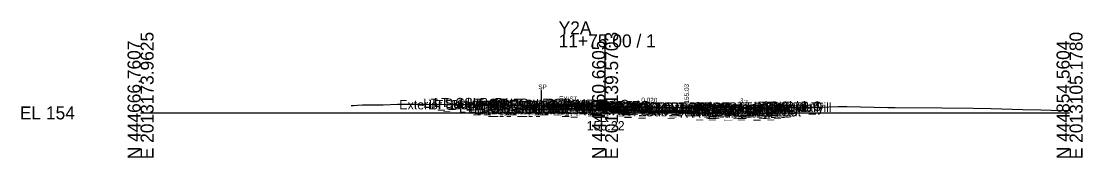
# Model space of a CAD drawing. Extents: x -26 to 203, y -10 to 5517.
# Drawn here: x -25.7 to 202.8, y 3490.3 to 3519.8 of the extents above; entities that cross this region are included whole.
import ezdxf

# ---------------------------------------------------------------- set-up
doc = ezdxf.new("R2010")
doc.units = 0
for name, color, linetype in [('Default', 7, 'Continuous'), ('Exist CMT Pavement', 7, 'Continuous'), ('Exist Cross Section Cell', 7, 'Continuous'), ('Exist XS Center Line Elevation Label', 7, 'Continuous'), ('Exist XS Ground Line', 7, 'Continuous'), ('Prop CMT Conc Surface', 7, 'Continuous'), ('Prop CMT Concrete Structures', 7, 'Continuous'), ('Prop CMT Pvmt Course 1', 7, 'Continuous'), ('Prop CMT Pvmt Course 1 CG', 7, 'Continuous'), ('Prop CMT Pvmt Course 2', 7, 'Continuous'), ('Prop CMT Pvmt Course 3', 7, 'Continuous'), ('Prop CMT Pvmt Surface', 7, 'Continuous'), ('Prop CMT Pvmt Wedge Surface 1', 7, 'Continuous'), ('Prop CMT Pvmt Wedge Surface 2', 7, 'Continuous'), ('Prop CMT Pvmt Wedge Surface 3', 7, 'Continuous'), ('Prop CMT Shear Line', 7, 'Continuous'), ('Prop CMT Slope Grass', 7, 'Continuous'), ('Prop CMT Subgrade Earthwork', 7, 'Continuous'), ('Prop XS Earthwork Shape', 7, 'Continuous'), ('Prop XS Hydro Elevations', 7, 'Continuous'), ('Prop XS SE Text', 7, 'Continuous'), ('Prop XS Side Slope Text', 7, 'Continuous'), ('Scratch_Level_0', 7, 'Continuous')]:
    doc.layers.add(name, color=color, linetype=linetype)

msp = doc.modelspace()

# ---------------------------------------------------------------- linework, layer by layer
at = {"layer": 'Exist CMT Pavement'}
msp.add_lwpolyline([(108.71, 3501.18), (102.91, 3501.28)], dxfattribs=at)
at = {"layer": 'Exist Cross Section Cell'}
for p, q in [((100, 3500), (100, 3516.95)), ((0, 3500), (100, 3500)), ((100, 3500), (200, 3500))]:
    msp.add_line(p, q, dxfattribs=at)
at = {"layer": 'Exist XS Ground Line'}
msp.add_lwpolyline([(45.34, 3501.58), (45.91, 3501.62), (46.67, 3501.66), (47.75, 3501.72), (49.39, 3501.73), (52.22, 3501.74), (55.33, 3501.87), (61.58, 3501.88), (65.98, 3501.85), (70.09, 3501.78), (75.85, 3501.71), (81.76, 3501.63), (82.53, 3501.62), (83.3, 3501.59), (84.88, 3501.52), (85.6, 3502.01), (86.18, 3501.93), (87.4, 3501.89), (90.91, 3501.91), (96.33, 3501.82), (97.35, 3501.79), (98.1, 3501.71), (98.82, 3501.2), (99.54, 3501.21), (100.23, 3501.23), (100.64, 3501.23), (101.31, 3501.23), (101.87, 3501.3), (107.82, 3501.18), (110.39, 3501.18), (113.57, 3501.21), (122.56, 3500.91), (126.51, 3500.76), (127.28, 3500.72), (128.49, 3500.65), (129, 3501.15), (130.13, 3501.15), (132.32, 3501.14), (134.31, 3501.13), (135.45, 3501.13), (146.24, 3501.26), (150.21, 3501.36), (152.02, 3501.36), (160.85, 3501.17), (161.84, 3501.15), (162.42, 3501.14), (172.49, 3501.1), (179.22, 3501.02), (183.14, 3500.96), (189.93, 3500.76), (193.79, 3500.65), (196.03, 3500.61), (200, 3500.55)], dxfattribs=at)
at = {"layer": 'Prop CMT Conc Surface'}
for points in [[(115.54, 3501.15), (117.54, 3501.03)], [(117.54, 3501.03), (117.54, 3501.53), (118.04, 3501.53)]]:
    msp.add_lwpolyline(points, dxfattribs=at)
at = {"layer": 'Prop CMT Concrete Structures'}
for points in [[(98.28, 3501.48), (102.91, 3501.4)], [(115.54, 3501.15), (117.54, 3501.03), (117.54, 3501.53), (118.04, 3501.53)], [(118.04, 3501.53), (118.04, 3500.52), (115.54, 3500.57)], [(115.54, 3500.57), (115.54, 3501.15)], [(127.66, 3501.73), (122.34, 3501.63)], [(122.34, 3501.63), (122.34, 3501.29)], [(122.34, 3501.29), (127.66, 3501.4)], [(127.66, 3501.4), (127.66, 3501.73)]]:
    msp.add_lwpolyline(points, dxfattribs=at)
at = {"layer": 'Prop CMT Pvmt Course 1'}
for points in [[(98.28, 3501.48), (86.29, 3501.6)], [(86.29, 3501.59), (86.29, 3501.42)], [(98.28, 3501.23), (98.28, 3501.48)], [(98.28, 3501.48), (102.91, 3501.4)], [(98.28, 3501.23), (98.28, 3501.48)], [(98.28, 3501.35), (98.28, 3501.23), (98.28, 3501.23)], [(102.91, 3501.15), (98.28, 3501.23)], [(102.91, 3501.4), (115.54, 3501.15)], [(102.91, 3501.15), (102.91, 3501.4)], [(102.91, 3501.4), (102.91, 3501.15)], [(102.91, 3501.28), (102.91, 3501.15), (102.91, 3501.15)], [(114.5, 3500.92), (102.91, 3501.15)], [(115.54, 3501.15), (115.54, 3500.9)], [(115.54, 3500.9), (114.5, 3500.92)]]:
    msp.add_lwpolyline(points, dxfattribs=at)
at = {"layer": 'Prop CMT Pvmt Course 1 CG'}
for points in [[(86.29, 3500.76), (86.29, 3501.09)], [(115.54, 3500.57), (118.54, 3500.51), (118.88, 3500.17)], [(115.54, 3500.23), (115.54, 3500.57)], [(118.88, 3500.17), (115.54, 3500.23)]]:
    msp.add_lwpolyline(points, dxfattribs=at)
at = {"layer": 'Prop CMT Pvmt Course 2'}
for points in [[(86.29, 3501.42), (86.29, 3501.09)], [(86.29, 3501.42), (98.28, 3501.23)], [(86.29, 3501.01), (86.29, 3501.01), (86.29, 3501.34), (86.29, 3501.34)], [(98.28, 3501.23), (102.91, 3501.15)], [(98.28, 3500.89), (98.28, 3501.23)], [(102.91, 3501.15), (102.91, 3500.82)], [(102.91, 3500.82), (98.28, 3500.89)], [(114.5, 3500.92), (115.54, 3500.9)], [(115.54, 3500.57), (114.5, 3500.59)], [(115.54, 3500.9), (115.54, 3500.57)]]:
    msp.add_lwpolyline(points, dxfattribs=at)
at = {"layer": 'Prop CMT Pvmt Course 3'}
for points in [[(86.29, 3501.09), (98.28, 3500.89)], [(98.28, 3500.56), (86.29, 3500.76)], [(98.28, 3500.89), (102.91, 3500.82)], [(98.28, 3500.56), (98.28, 3500.89)], [(102.91, 3500.49), (98.28, 3500.56)], [(102.91, 3500.82), (102.91, 3500.49)], [(102.91, 3500.82), (114.5, 3500.59)], [(115.54, 3500.23), (102.91, 3500.49)], [(114.5, 3500.59), (115.54, 3500.57)], [(115.54, 3500.57), (115.54, 3500.23)]]:
    msp.add_lwpolyline(points, dxfattribs=at)
at = {"layer": 'Prop CMT Pvmt Surface'}
for points in [[(98.28, 3501.48), (86.29, 3501.6)], [(98.28, 3501.48), (102.91, 3501.4)], [(102.91, 3501.4), (115.54, 3501.15)]]:
    msp.add_lwpolyline(points, dxfattribs=at)
at = {"layer": 'Prop CMT Pvmt Wedge Surface 1'}
for points in [[(98.28, 3501.48), (98.28, 3501.23), (98.28, 3501.23), (98.28, 3501.35)], [(102.91, 3501.4), (102.91, 3501.15), (102.91, 3501.15), (102.91, 3501.28)], [(115.54, 3500.9), (115.54, 3501.15)], [(114.5, 3500.92), (115.54, 3500.9)]]:
    msp.add_lwpolyline(points, dxfattribs=at)
at = {"layer": 'Prop CMT Pvmt Wedge Surface 2'}
for points in [[(98.28, 3501.48), (98.28, 3501.23)], [(102.91, 3501.4), (102.91, 3501.15)], [(115.54, 3500.9), (115.54, 3501.15)]]:
    msp.add_lwpolyline(points, dxfattribs=at)
at = {"layer": 'Prop CMT Pvmt Wedge Surface 3'}
for points in [[(98.28, 3501.48), (98.28, 3500.89)], [(102.91, 3501.4), (102.91, 3500.82)], [(115.54, 3500.57), (115.54, 3501.15)]]:
    msp.add_lwpolyline(points, dxfattribs=at)
at = {"layer": 'Prop CMT Shear Line'}
msp.add_line((86.29, 3499.9), (86.29, 3504.99), dxfattribs=at)
at = {"layer": 'Prop CMT Slope Grass'}
for points in [[(118.04, 3501.53), (127.66, 3501.72)], [(127.66, 3501.72), (128.16, 3501.73), (129.92, 3501.15)]]:
    msp.add_lwpolyline(points, dxfattribs=at)
at = {"layer": 'Prop CMT Subgrade Earthwork'}
msp.add_line((86.29, 3500.76), (86.29, 3501.93), dxfattribs=at)
for points in [[(115.54, 3500.23), (118.88, 3500.17), (120.29, 3501.58)], [(86.29, 3500.76), (98.28, 3500.56)], [(98.28, 3500.56), (102.91, 3500.49)], [(102.91, 3500.49), (115.54, 3500.23)]]:
    msp.add_lwpolyline(points, dxfattribs=at)
at = {"layer": 'Prop XS Earthwork Shape'}
for points in [[(98.28, 3501.48), (86.29, 3501.6), (86.29, 3501.93), (87.4, 3501.89), (90.91, 3501.91), (96.33, 3501.82), (97.35, 3501.79), (98.1, 3501.71), (98.28, 3501.58)], [(102.91, 3501.28), (107.82, 3501.18), (108.71, 3501.18), (110.39, 3501.18), (112.93, 3501.2), (115.54, 3501.15), (115.54, 3500.57), (118.04, 3500.52), (118.04, 3501.06), (119.72, 3501.01), (118.88, 3500.17), (115.54, 3500.23), (102.91, 3500.49), (98.28, 3500.56), (86.29, 3500.76), (86.29, 3501.6), (98.28, 3501.48), (98.43, 3501.48), (98.82, 3501.2), (99.54, 3501.21), (100.23, 3501.23), (100.64, 3501.23), (101.31, 3501.23), (101.87, 3501.3)], [(98.28, 3501.58), (98.28, 3501.48), (98.43, 3501.48)], [(100.64, 3501.23), (101.31, 3501.23), (101.87, 3501.3), (102.91, 3501.28), (108.71, 3501.18), (110.39, 3501.18), (112.93, 3501.2), (102.91, 3501.4), (98.43, 3501.48), (98.82, 3501.2), (99.54, 3501.21), (100.23, 3501.23)], [(113.57, 3501.21), (115.54, 3501.15), (112.93, 3501.2)], [(115.54, 3501.15), (115.79, 3501.14), (117.54, 3501.03), (117.54, 3501.08), (118.04, 3501.06), (118.04, 3500.52), (115.54, 3500.57)], [(115.79, 3501.14), (117.54, 3501.08), (117.54, 3501.03)], [(126.51, 3500.76), (127.28, 3500.72), (128.49, 3500.65), (129, 3501.15), (129.92, 3501.15), (128.16, 3501.73), (127.66, 3501.72), (127.66, 3501.4), (122.34, 3501.29), (122.34, 3501.63), (120.29, 3501.58), (119.72, 3501.01), (122.56, 3500.91)]]:
    msp.add_lwpolyline(points, close=True, dxfattribs=at)

# ---------------------------------------------------------------- texts
at = {"layer": 'Default'}
msp.add_text('-', height=0.0001, dxfattribs=at).set_placement((0, 3500))
at = {"layer": 'Exist Cross Section Cell'}
for s, p in [('Y2A', (90, 3516.95)), ('11+75.00 / 1', (90, 3514.15)), ('EL 154', (-26, 3498.6))]:
    msp.add_text(s, height=2.8, dxfattribs=at).set_placement(p)
for s, p in [('E 2013173.9625', (2.8, 3490)), ('E 2013139.5703', (102.8, 3490)), ('E 2013105.1780', (202.8, 3490)), ('N 444666.7607', (0, 3490)), ('N 444760.6605', (100, 3490)), ('N 444854.5604', (200, 3490))]:
    msp.add_text(s, height=2.8, rotation=90, dxfattribs=at).set_placement(p)
at = {"layer": 'Exist XS Center Line Elevation Label'}
msp.add_text('155.22', height=2, dxfattribs=at).set_placement((96.03, 3496.22))
at = {"layer": 'Prop XS Hydro Elevations'}
msp.add_text('SP', height=1, dxfattribs=at).set_placement((85.62, 3505.12))
msp.add_text('155.03', height=1, rotation=90, dxfattribs=at).set_placement((118.04, 3502.03))
at = {"layer": 'Prop XS SE Text'}
for s, rotation, p in [('EXIST', 359.4271, (90.08, 3502.56)), ('0.020', 358.8542, (107.79, 3502.31))]:
    msp.add_text(s, height=1, rotation=rotation, dxfattribs=at).set_placement(p)
at = {"layer": 'Prop XS Side Slope Text'}
msp.add_text('3:1', height=1, rotation=341.5668, dxfattribs=at).set_placement((128.84, 3502.29))
at = {"layer": 'Scratch_Level_0'}
for s, p in [('Exterior Boundary', (55.7, 3500.76)), ('LT_Sub_Trench_Out_DLT', (60.87, 3501.09)), ('LT_Slope_Fill', (62.08, 3500.76)), ('LT_CSLP_Pnt', (63.17, 3501.24)), ('LT_CG1_Shelf_Out', (68.55, 3500.06)), ('LT_PV_Sub_Tie_Out', (69.96, 3500.63)), ('LT_CG_Top_Face', (70.26, 3501.05)), ('LT_CG_Top_BOC', (70.78, 3501.05)), ('LT_CG_Bot_BOC', (70.81, 3500.05)), ('LT_CG_Top_Gut', (71.24, 3500.55)), ('LT_Sub_OEOP', (71.78, 3499.73)), ('LT_Sub_OEOT_CG', (72.37, 3499.69)), ('LT_PV_OEEOP_EG', (72.54, 3500.62)), ('LT_Sub_OEEOP', (74.21, 3499.69)), ('LT_PV2_OEEOP', (74.31, 3500.36)), ('LT_PV3_OEEOP', (74.31, 3500.03)), ('LT_PV1_OEEOP', (74.87, 3500.49)), ('LT_CG_Bot_IE', (74.91, 3500.03)), ('LT_Sub_OEOT', (75.08, 3499.69)), ('LT_PV2_OEOT', (75.17, 3500.36)), ('LT_PV3_OEOT', (75.17, 3500.03)), ('LT_PV1_OEOT', (75.74, 3500.61)), ('LT_PV_EG_TestPt', (78.05, 3500.89)), ('LT_PV_IEEOP_EG', (86.47, 3500.58)), ('LT_PV2_IEEOP', (88.23, 3500.23)), ('LT_PV3_IEEOP', (88.23, 3499.89)), ('LT_PV1_IEEOP', (88.8, 3500.35)), ('LT_PV2_PGL1', (89.16, 3500.23)), ('LT_PV3_PGL1', (89.16, 3499.89)), ('LT_PV2_PGL', (89.49, 3500.23)), ('LT_PV3_PGL', (89.49, 3499.89)), ('LT_PV4_PGL', (89.49, 3499.56)), ('LT_PV1_PGL', (90.06, 3500.48)), ('MI_Face In', (90.18, 3500.64)), ('RT_PV_IEEOP_EG', (91.05, 3500.28)), ('MI_Top In', (91.89, 3500.89)), ('RT_PV2_IEEOP', (92.81, 3500.15)), ('RT_PV3_IEEOP', (92.81, 3499.82)), ('MI_Face Out', (93.17, 3500.57)), ('MI_Top Out', (93.38, 3500.82)), ('RT_PV1_IEEOP', (93.38, 3500.28)), ('MI_Crown', (93.67, 3500.93)), ('RT_PV2_PGL1', (93.74, 3500.15)), ('RT_PV3_PGL1', (93.74, 3499.82)), ('RT_PV2_PGL', (94.07, 3500.15)), ('RT_PV3_PGL', (94.07, 3499.82)), ('RT_PV4_PGL', (94.07, 3499.49)), ('MI_Bot Out', (94.17, 3500.4)), ('RT_PV1_PGL', (94.64, 3500.4)), ('RT_PV_EG_TestPt', (95.07, 3500.18)), ('RT_PV_Sub_Tie_Out', (99.38, 3500.18)), ('RT_PV_OEEOP_EG', (102, 3500.18)), ('RT_Sub_OEEOP', (103.67, 3499.25)), ('RT_PV2_OEEOP', (103.76, 3499.92)), ('RT_PV3_OEEOP', (103.76, 3499.59)), ('RT_PV1_OEEOP', (104.33, 3500.05)), ('RT_Sub_Trench_Out_DLT', (114.02, 3500.31)), ('RT_CG_Top_Face', (117.96, 3500.27)), ('RT_CG1_Shelf_Out', (118.25, 3499.24)), ('RT_CG_Bot_IE', (118.62, 3499.3)), ('RT_PV2_OEOT', (118.88, 3499.64)), ('RT_PV3_OEOT', (118.88, 3499.3)), ('RT_CG_Top_Gut', (118.94, 3499.77)), ('RT_PV1_OEOT', (119.44, 3499.89)), ('RT_CG_Top_BOC', (119.49, 3500.27)), ('RT_CG_Bot_BOC', (119.52, 3499.25)), ('Exterior Boundary', (125.65, 3500.21)), ('Exterior Boundary', (125.65, 3500.21)), ('RT_Slope_Fill', (131.98, 3500.21)), ('RT_Slope_Fill', (131.98, 3500.21)), ('RT_Shld_O', (132.79, 3500.45)), ('CSLP_Pnt', (133.62, 3500.46)), ('RT_Sub_OEOT_CG', (116.07, 3498.97)), ('RT_Sub_OEOT', (118.78, 3498.97)), ('RT_Sub_OEOP', (122.15, 3498.9))]:
    msp.add_text(s, height=2, dxfattribs=at).set_placement(p)

doc.saveas('drawing.dxf')
